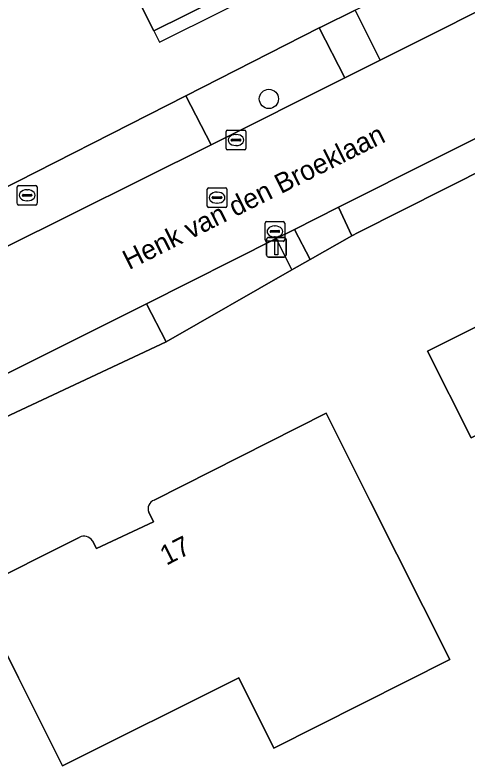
# Model space of a CAD drawing. Extents: x 157320 to 158835, y 386650 to 388491.
# Drawn here: x 158373.46 to 158396.47, y 387023.56 to 387061.67 of the extents above; entities that cross this region are included whole.
import ezdxf

# ---------------------------------------------------------------- set-up
doc = ezdxf.new("R2010")
doc.units = 0
for name, color, linetype in [('IMGEO_Berm_groen', 7, 'Continuous'), ('IMGEO_Boom', 7, 'Continuous'), ('IMGEO_Brandkraan', 7, 'Continuous'), ('IMGEO_Erf', 7, 'Continuous'), ('IMGEO_Groenvoorziening', 7, 'Continuous'), ('IMGEO_Kolk', 7, 'Continuous'), ('IMGEO_Lichtmast', 7, 'Continuous'), ('IMGEO_Openbare_ruimte_label', 7, 'Continuous'), ('IMGEO_Pand', 7, 'Continuous'), ('IMGEO_Pand_nummerreeks', 7, 'Continuous'), ('IMGEO_Pand_overbouw', 7, 'Continuous'), ('IMGEO_Rijbaan_lokaal_gesloten', 7, 'Continuous'), ('IMGEO_Rioolput', 7, 'Continuous'), ('IMGEO_Voetpad_open', 7, 'Continuous')]:
    doc.layers.add(name, color=color, linetype=linetype)

msp = doc.modelspace()

# ---------------------------------------------------------------- linework, layer by layer
at = {"layer": 'IMGEO_Berm_groen'}
for points in [[(158415.179, 387070.996), (158413.936, 387073.552), (158390.827, 387061.949), (158390.738, 387061.906), (158392.005, 387059.378)], [(158390.207, 387058.483), (158388.915, 387061.021), (158382.133, 387057.57), (158383.425, 387055.083)]]:
    msp.add_lwpolyline(points, close=True, dxfattribs=at)
at = {"layer": 'IMGEO_Boom'}
msp.add_circle((158386.354, 387057.411), 0.489, dxfattribs=at)
at = {"layer": 'IMGEO_Brandkraan'}
for p, q in [((158373.578, 387052.095), (158373.578, 387052.947)), ((158373.653, 387053.021), (158374.505, 387053.021)), ((158374.066, 387052.801), (158374.091, 387052.801)), ((158374.579, 387052.947), (158374.579, 387052.095)), ((158373.837, 387052.515), (158373.837, 387052.527)), ((158374.275, 387052.478), (158373.877, 387052.478)), ((158373.88, 387052.564), (158374.278, 387052.564)), ((158374.321, 387052.527), (158374.321, 387052.515)), ((158374.505, 387052.021), (158373.653, 387052.021)), ((158374.089, 387052.241), (158374.064, 387052.241))]:
    msp.add_line(p, q, dxfattribs=at)
for points in [[(158373.578, 387052.095), (158373.578, 387052.947)], [(158373.653, 387053.021), (158374.505, 387053.021)], [(158374.579, 387052.947), (158374.579, 387052.095)], [(158374.505, 387052.021), (158373.653, 387052.021)]]:
    msp.add_lwpolyline(points, dxfattribs=at)
for centre, radius, start, end in [((158373.655, 387052.945), 0.0765, 91.552, 178.448), ((158373.655, 387052.945), 0.0765, 91.552, 178.448), ((158374.503, 387052.945), 0.0765, 1.552, 88.448), ((158374.503, 387052.945), 0.0765, 1.552, 88.448), ((158373.877, 387052.524), 0.0403, 85.8775, 175.7526), ((158373.874, 387052.514), 0.0366, 178.938, 274.7102), ((158374.278, 387052.521), 0.043, 264.8664, 352.4533), ((158374.282, 387052.526), 0.0386, 1.7309, 96.639), ((158373.655, 387052.097), 0.0765, 181.552, 268.448), ((158373.655, 387052.097), 0.0765, 181.552, 268.448), ((158374.503, 387052.097), 0.0765, 271.552, 358.448), ((158374.503, 387052.097), 0.0765, 271.552, 358.448)]:
    msp.add_arc(centre, radius, start, end, dxfattribs=at)
for centre, major_axis, ratio, start_param, end_param in [((158374.065, 387052.521), (-0.387, 0.002), 0.722429, 4.712389, 7.853982), ((158374.09, 387052.521), (-0.39, 0.002), 0.717154, 1.570796, 4.712389)]:
    msp.add_ellipse(centre, major_axis=major_axis, ratio=ratio, start_param=start_param, end_param=end_param, dxfattribs=at)
at = {"layer": 'IMGEO_Erf'}
for points in [[(158388.268, 387078.893), (158391.685, 387072.039), (158393.916, 387067.564), (158389.603, 387065.402), (158389.884, 387064.825), (158389.504, 387064.647), (158388.928, 387065.804), (158387.121, 387064.893), (158387.697, 387063.736), (158387.305, 387063.54), (158387.013, 387064.1), (158380.508, 387060.865), (158378.27, 387065.337), (158374.837, 387072.198)], [(158417.327, 387040.195), (158419.528, 387041.292), (158421.552, 387037.23), (158416.757, 387034.84), (158414.612, 387035.762), (158413.517, 387037.946), (158410.339, 387036.353), (158409.501, 387038), (158408.757, 387037.621), (158406.694, 387038.341), (158406.331, 387039.063), (158401.738, 387036.758), (158399.326, 387041.565), (158396.622, 387040.208), (158394.413, 387044.61), (158402.024, 387048.415), (158402.429, 387047.619), (158404.48, 387048.662), (158405.462, 387046.686), (158412.377, 387050.125)]]:
    msp.add_lwpolyline(points, close=True, dxfattribs=at)
for points in [[(158290.161, 387072.435), (158301.269, 387050.069), (158303.264, 387046.138), (158306.491, 387039.618), (158308.276, 387037.566), (158310.63, 387035.776), (158320.234, 387028.475), (158323.4, 387028.136), (158326.039, 387029.409), (158326.995, 387029.871), (158334.724, 387033.795), (158337.352, 387035.129), (158344.798, 387038.91), (158348.028, 387040.523), (158352.163, 387042.718), (158357.989, 387045.538), (158371.672, 387052.258), (158382.133, 387057.57), (158388.915, 387061.021), (158389.023, 387061.076), (158390.738, 387061.906)], [(158424.326, 387067.316), (158409.775, 387060.049), (158407.876, 387059.101), (158404.527, 387057.508), (158404.288, 387057.387), (158390.893, 387050.635), (158390.572, 387050.456), (158388.447, 387049.268), (158387.528, 387048.741), (158381.13, 387045.08), (158365.561, 387037.786), (158361.263, 387035.597), (158358.348, 387034.192), (158355.614, 387032.874), (158352.957, 387031.592), (158341.848, 387026.236), (158336.855, 387023.731)], [(158380.522, 387037.056), (158389.257, 387041.461), (158391.504, 387036.995), (158395.547, 387028.956)], [(158377.395, 387034.993), (158377.601, 387034.6), (158380.501, 387035.956), (158380.254, 387036.432)], [(158395.547, 387028.956), (158386.611, 387024.46), (158384.823, 387028.036), (158375.874, 387023.56), (158373.639, 387028.029), (158371.403, 387032.5), (158376.725, 387035.16)]]:
    msp.add_lwpolyline(points, dxfattribs=at)
for centre, radius, start, end in [((158380.688, 387036.615), 0.471, 110.5955, 202.9187), ((158376.967, 387034.704), 0.516, 34.0342, 117.9738)]:
    msp.add_arc(centre, radius, start, end, dxfattribs=at)
at = {"layer": 'IMGEO_Groenvoorziening'}
for points in [[(158404.288, 387057.387), (158403.591, 387058.779), (158390.165, 387052.056), (158389.889, 387051.918), (158390.572, 387050.456), (158390.893, 387050.635)], [(158388.447, 387049.268), (158387.648, 387050.792), (158386.719, 387050.325), (158387.528, 387048.741)], [(158365.561, 387037.786), (158381.13, 387045.08), (158380.131, 387047.014), (158364.741, 387039.333)]]:
    msp.add_lwpolyline(points, close=True, dxfattribs=at)
at = {"layer": 'IMGEO_Kolk'}
for p, q in [((158384.183, 387054.899), (158384.183, 387055.751)), ((158384.258, 387055.825), (158385.11, 387055.825)), ((158385.184, 387055.751), (158385.184, 387054.899)), ((158384.485, 387055.368), (158384.883, 387055.368)), ((158384.671, 387055.605), (158384.696, 387055.605)), ((158384.442, 387055.319), (158384.442, 387055.331)), ((158384.88, 387055.282), (158384.482, 387055.282)), ((158384.694, 387055.045), (158384.669, 387055.045)), ((158384.926, 387055.331), (158384.926, 387055.319)), ((158385.11, 387054.825), (158384.258, 387054.825)), ((158386.234, 387051.184), (158387.086, 387051.184)), ((158386.159, 387050.258), (158386.159, 387051.11)), ((158386.647, 387050.964), (158386.672, 387050.964)), ((158387.16, 387051.11), (158387.16, 387050.258)), ((158386.418, 387050.678), (158386.418, 387050.69)), ((158386.856, 387050.641), (158386.458, 387050.641)), ((158386.461, 387050.727), (158386.859, 387050.727)), ((158386.67, 387050.404), (158386.645, 387050.404)), ((158386.902, 387050.69), (158386.902, 387050.678)), ((158387.086, 387050.184), (158386.234, 387050.184))]:
    msp.add_line(p, q, dxfattribs=at)
for points in [[(158384.183, 387054.899), (158384.183, 387055.751)], [(158384.258, 387055.825), (158385.11, 387055.825)], [(158385.184, 387055.751), (158385.184, 387054.899)], [(158385.11, 387054.825), (158384.258, 387054.825)], [(158386.234, 387051.184), (158387.086, 387051.184)], [(158386.159, 387050.258), (158386.159, 387051.11)], [(158387.16, 387051.11), (158387.16, 387050.258)], [(158387.086, 387050.184), (158386.234, 387050.184)]]:
    msp.add_lwpolyline(points, dxfattribs=at)
for centre, radius, start, end in [((158384.26, 387055.749), 0.0765, 91.552, 178.448), ((158384.26, 387055.749), 0.0765, 91.552, 178.448), ((158385.108, 387055.749), 0.0765, 1.552, 88.448), ((158385.108, 387055.749), 0.0765, 1.552, 88.448), ((158384.482, 387055.328), 0.0403, 85.8775, 175.7526), ((158384.887, 387055.33), 0.0386, 1.7309, 96.639), ((158384.479, 387055.318), 0.0366, 178.938, 274.7102), ((158384.883, 387055.325), 0.043, 264.8664, 352.4533), ((158384.26, 387054.901), 0.0765, 181.552, 268.448), ((158384.26, 387054.901), 0.0765, 181.552, 268.448), ((158385.108, 387054.901), 0.0765, 271.552, 358.448), ((158385.108, 387054.901), 0.0765, 271.552, 358.448), ((158386.236, 387051.108), 0.0765, 91.552, 178.448), ((158386.236, 387051.108), 0.0765, 91.552, 178.448), ((158387.084, 387051.108), 0.0765, 1.552, 88.448), ((158387.084, 387051.108), 0.0765, 1.552, 88.448), ((158386.458, 387050.687), 0.0403, 85.8775, 175.7526), ((158386.455, 387050.677), 0.0366, 178.938, 274.7102), ((158386.859, 387050.684), 0.043, 264.8664, 352.4533), ((158386.863, 387050.689), 0.0386, 1.7309, 96.639), ((158386.236, 387050.26), 0.0765, 181.552, 268.448), ((158386.236, 387050.26), 0.0765, 181.552, 268.448), ((158387.084, 387050.26), 0.0765, 271.552, 358.448), ((158387.084, 387050.26), 0.0765, 271.552, 358.448)]:
    msp.add_arc(centre, radius, start, end, dxfattribs=at)
for centre, major_axis, ratio, start_param, end_param in [((158384.67, 387055.325), (-0.387, 0.002), 0.722429, 4.712389, 7.853982), ((158384.695, 387055.325), (-0.39, 0.002), 0.717154, 1.570796, 4.712389), ((158386.646, 387050.684), (-0.387, 0.002), 0.722429, 4.712389, 7.853982), ((158386.671, 387050.684), (-0.39, 0.002), 0.717154, 1.570796, 4.712389)]:
    msp.add_ellipse(centre, major_axis=major_axis, ratio=ratio, start_param=start_param, end_param=end_param, dxfattribs=at)
at = {"layer": 'IMGEO_Lichtmast'}
for p, q in [((158386.337, 387050.381), (158387.127, 387050.381)), ((158387.127, 387050.381), (158386.337, 387050.381)), ((158386.237, 387049.481), (158386.237, 387050.281)), ((158386.237, 387050.281), (158386.237, 387049.481)), ((158387.227, 387050.281), (158387.227, 387049.481)), ((158387.227, 387049.481), (158387.227, 387050.281)), ((158387.127, 387049.381), (158386.337, 387049.381)), ((158386.337, 387049.381), (158387.127, 387049.381))]:
    msp.add_line(p, q, dxfattribs=at)
msp.add_lwpolyline([(158386.657, 387050.256), (158386.807, 387050.256), (158386.807, 387049.506), (158386.657, 387049.506), (158386.657, 387050.256)], dxfattribs=at)
for centre, start, end in [((158386.337, 387050.281), 90, 180), ((158386.337, 387050.281), 90, 180), ((158387.127, 387050.281), 0, 90), ((158387.127, 387050.281), 360, 90), ((158386.337, 387049.481), 180, 270), ((158386.337, 387049.481), 180, 270), ((158387.127, 387049.481), 270, 0), ((158387.127, 387049.481), 270, 0)]:
    msp.add_arc(centre, 0.1, start, end, dxfattribs=at)
at = {"layer": 'IMGEO_Pand'}
for points in [[(158389.603, 387065.402), (158393.916, 387067.564), (158391.685, 387072.039), (158388.268, 387078.893), (158374.837, 387072.198), (158378.27, 387065.337), (158380.508, 387060.865), (158387.013, 387064.1), (158387.305, 387063.54), (158387.697, 387063.736), (158387.121, 387064.893), (158388.928, 387065.804), (158389.504, 387064.647), (158389.884, 387064.825)], [(158421.552, 387037.23), (158419.528, 387041.292), (158417.327, 387040.195), (158412.377, 387050.125), (158405.462, 387046.686), (158404.48, 387048.662), (158402.429, 387047.619), (158402.024, 387048.415), (158394.413, 387044.61), (158396.622, 387040.208), (158399.326, 387041.565), (158401.738, 387036.758), (158406.331, 387039.063), (158406.694, 387038.341), (158408.757, 387037.621), (158409.501, 387038), (158410.339, 387036.353), (158413.517, 387037.946), (158414.612, 387035.762), (158416.757, 387034.84)]]:
    msp.add_lwpolyline(points, close=True, dxfattribs=at)
for points in [[(158376.725, 387035.16), (158371.403, 387032.5), (158373.639, 387028.029), (158375.874, 387023.56), (158384.823, 387028.036), (158386.611, 387024.46), (158395.547, 387028.956), (158391.504, 387036.995), (158389.257, 387041.461), (158380.522, 387037.056)], [(158380.254, 387036.432), (158380.501, 387035.956), (158377.601, 387034.6), (158377.395, 387034.993)]]:
    msp.add_lwpolyline(points, dxfattribs=at)
for centre, radius, start, end in [((158380.688, 387036.615), 0.471, 110.5955, 202.9187), ((158376.967, 387034.704), 0.516, 34.0342, 117.9738)]:
    msp.add_arc(centre, radius, start, end, dxfattribs=at)
at = {"layer": 'IMGEO_Pand_overbouw'}
msp.add_lwpolyline([(158380.508, 387060.865), (158380.798, 387060.286), (158387.305, 387063.54), (158387.013, 387064.1)], close=True, dxfattribs=at)
at = {"layer": 'IMGEO_Rijbaan_lokaal_gesloten'}
for points in [[(158415.179, 387070.996), (158392.005, 387059.378), (158390.207, 387058.483), (158383.425, 387055.083), (158372.885, 387049.837), (158359.245, 387043.002), (158353.495, 387040.129), (158349.279, 387038.02), (158346.051, 387036.405), (158338.557, 387032.656)], [(158336.2, 387025.079), (158341.18, 387027.566), (158352.213, 387033.09), (158354.869, 387034.42), (158359.307, 387036.641), (158360.393, 387037.185), (158364.741, 387039.333), (158380.131, 387047.014), (158386.719, 387050.325), (158387.648, 387050.792), (158389.889, 387051.918), (158390.165, 387052.056), (158403.591, 387058.779), (158403.798, 387058.883), (158407.127, 387060.538), (158409.052, 387061.498), (158423.604, 387068.756)]]:
    msp.add_lwpolyline(points, dxfattribs=at)
at = {"layer": 'IMGEO_Rioolput'}
for p, q in [((158383.223, 387051.974), (158383.223, 387052.826)), ((158383.298, 387052.9), (158384.15, 387052.9)), ((158383.711, 387052.68), (158383.736, 387052.68)), ((158384.224, 387052.826), (158384.224, 387051.974)), ((158383.482, 387052.394), (158383.482, 387052.406)), ((158383.92, 387052.357), (158383.522, 387052.357)), ((158383.525, 387052.443), (158383.923, 387052.443)), ((158383.966, 387052.406), (158383.966, 387052.394)), ((158383.734, 387052.12), (158383.709, 387052.12)), ((158384.15, 387051.9), (158383.298, 387051.9))]:
    msp.add_line(p, q, dxfattribs=at)
for points in [[(158383.223, 387051.974), (158383.223, 387052.826)], [(158383.298, 387052.9), (158384.15, 387052.9)], [(158384.224, 387052.826), (158384.224, 387051.974)], [(158384.15, 387051.9), (158383.298, 387051.9)]]:
    msp.add_lwpolyline(points, dxfattribs=at)
for centre, radius, start, end in [((158383.3, 387052.824), 0.0765, 91.552, 178.448), ((158383.3, 387052.824), 0.0765, 91.552, 178.448), ((158384.148, 387052.824), 0.0765, 1.552, 88.448), ((158384.148, 387052.824), 0.0765, 1.552, 88.448), ((158383.522, 387052.403), 0.0403, 85.8775, 175.7526), ((158383.519, 387052.393), 0.0366, 178.938, 274.7102), ((158383.923, 387052.4), 0.043, 264.8664, 352.4533), ((158383.927, 387052.405), 0.0386, 1.7309, 96.639), ((158383.3, 387051.976), 0.0765, 181.552, 268.448), ((158383.3, 387051.976), 0.0765, 181.552, 268.448), ((158384.148, 387051.976), 0.0765, 271.552, 358.448), ((158384.148, 387051.976), 0.0765, 271.552, 358.448)]:
    msp.add_arc(centre, radius, start, end, dxfattribs=at)
for centre, major_axis, ratio, start_param, end_param in [((158383.71, 387052.4), (-0.387, 0.002), 0.722429, 4.712389, 7.853982), ((158383.735, 387052.4), (-0.39, 0.002), 0.717154, 1.570796, 4.712389)]:
    msp.add_ellipse(centre, major_axis=major_axis, ratio=ratio, start_param=start_param, end_param=end_param, dxfattribs=at)
at = {"layer": 'IMGEO_Voetpad_open'}
for points in [[(158390.738, 387061.906), (158389.023, 387061.076), (158388.915, 387061.021), (158390.207, 387058.483), (158392.005, 387059.378)], [(158383.425, 387055.083), (158382.133, 387057.57), (158371.672, 387052.258), (158372.885, 387049.837)], [(158389.889, 387051.918), (158387.648, 387050.792), (158388.447, 387049.268), (158390.572, 387050.456)], [(158381.13, 387045.08), (158387.528, 387048.741), (158386.719, 387050.325), (158380.131, 387047.014)]]:
    msp.add_lwpolyline(points, close=True, dxfattribs=at)

# ---------------------------------------------------------------- texts
at = {"layer": 'IMGEO_Openbare_ruimte_label'}
msp.add_text('Henk van den Broeklaan', height=1, rotation=26.5651, dxfattribs=at).set_placement((158379.249, 387048.718))
at = {"layer": 'IMGEO_Pand_nummerreeks'}
msp.add_text('17', height=1, rotation=26.6523, dxfattribs=at).set_placement((158381.144, 387033.719))

doc.saveas('drawing.dxf')
